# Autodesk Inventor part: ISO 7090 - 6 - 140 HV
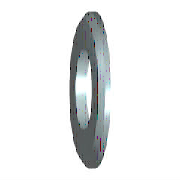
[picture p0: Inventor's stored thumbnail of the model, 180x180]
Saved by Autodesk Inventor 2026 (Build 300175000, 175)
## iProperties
IsCustomPart: 1
Created: 2022-02
Part Number: ISO 7090 - 6 - 140 HV
Material: Steel, Mild
Description: Plain washers, chamfered - Normal series - Product grade A
Document SubType Name: Modeling
Standard: ISO 7090
Designer: Lars Bertram Pedersen
Standard Revision: Second edition 2000-06-01
Standards Organization: ISO
Language: en-US
Size Designation: 6 - 140 HV
Categories: <MemberInstance><Categories><Category DisplayName="Fasteners" InternalName="e4da775c-781d-43d5-af7c-5136215cf5a6" Mnemonic="FSTN"><Category DisplayName="Washers
Density: 7.85 g/cm^3
Appearance: Semi-Polished
Mass: 0.925957 g
Surface Area: 2.35844 cm^2
Volume: 0.117956 cm^3
Stock Number: Lager
Author: Lars Bertram Pedersen
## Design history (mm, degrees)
body "Solid1"
sketch "Sketch"
  geometry: C1 r 6 at (0, 0); C2 r 3.2 at (0, 0); 1 further point
  constraints: 2 centre point, 2 coincident
  dimensions: "d0" = 6.4 diameter of C2 (= SD1); "d1" = 12 diameter of C1 (= SD2)
extrude "Body" new body sketch "Sketch" distance "d2" = 1.6 (= SD); taper "d3" = 0 deg
workaxis "Work Axis1"
workplane "Work Plane1"
chamfer "Chamfer" distance "d4" = 0.8 (= PHH); stored, may be unused: angle "d5" = 45 deg, second distance "d8" = 0.8 (= PHH)
other parameters: "SD1" = 6.4 [user parameter; used in 1 equation term], "SD2" = 12 [user parameter; used in 1 equation term], "SD" = 1.6 [user parameter; used in 1 equation term], "PHH" = 0.8 [user parameter; used in 2 equation terms], "FAWI" = 45 deg [user parameter], "d6" = 0, "d7" = 0, "d9" = 0, "d10" = 0, "NND" = 6 [user parameter]
